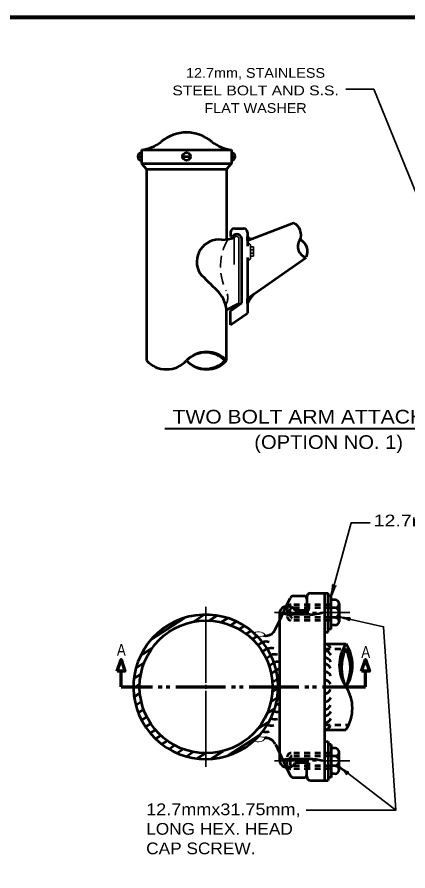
# Model space of a CAD drawing. Extents: x -32 to 824, y -12 to 532.
# Drawn here: x 407.2 to 527.1, y 262.9 to 525.2 of the extents above; entities that cross this region are included whole.
import ezdxf
from ezdxf.enums import TextEntityAlignment as Align

# ---------------------------------------------------------------- set-up
doc = ezdxf.new("R2010")
doc.units = 0
doc.header["$LTSCALE"] = 1.2
doc.header["$PDMODE"] = 32
doc.header["$PDSIZE"] = 0.6
for name, pattern in [('LONG_DASHED', [7.5, 6, -1.5]), ('MEDIUM_DASHED', [4.5, 3, -1.5]), ('SHORT_DASHED', [2.7, 1.5, -1.2])]:
    doc.linetypes.add(name, pattern=pattern)
doc.layers.add('1', color=7, linetype='Continuous', lineweight=13)

msp = doc.modelspace()

# ---------------------------------------------------------------- linework, layer by layer
at = {"layer": '1', "lineweight": 35}
for p, q in [((516.646, 503.069), (508.139, 503.069)), ((535.927, 455.696), (516.646, 503.069)), ((473.866, 449.258), (473.866, 457.442)), ((475.218, 437.258), (475.218, 457.058)), ((478.792, 451.117), (478.792, 455.136)), ((479.703, 453.725), (478.803, 453.725)), ((479.703, 452.707), (478.803, 452.707)), ((479.703, 451.807), (478.803, 451.807)), ((465.108, 320.687), (465.108, 344.049)), ((486.209, 342.287), (496.709, 342.287)), ((497.909, 342.287), (499.109, 342.287)), ((500.309, 342.287), (509.309, 342.287)), ((465.108, 318.887), (465.108, 320.087)), ((465.108, 294.849), (465.108, 318.287)), ((486.209, 296.687), (496.709, 296.687)), ((497.909, 296.687), (499.109, 296.687)), ((500.309, 296.687), (509.309, 296.687))]:
    msp.add_line(p, q, dxfattribs=at)
at = {"layer": '1', "lineweight": 53}
for p, q in [((445.409, 484.487), (473.009, 484.487)), ((445.409, 484.487), (445.409, 480.287)), ((473.009, 484.487), (473.009, 480.287)), ((444.216, 482.387), (445.109, 482.387)), ((445.409, 480.287), (473.009, 480.287)), ((445.409, 480.287), (446.909, 478.487)), ((458.301, 482.387), (460.101, 482.387)), ((473.009, 480.287), (471.509, 478.487)), ((473.309, 482.387), (474.153, 482.387)), ((446.909, 478.487), (446.909, 419.687)), ((446.909, 478.487), (471.509, 478.487)), ((471.509, 478.487), (471.509, 456.894)), ((477.889, 456.545), (492.012, 461.967)), ((472.709, 459.074), (472.709, 457.836)), ((473.909, 460.274), (476.689, 460.274)), ((477.889, 459.074), (477.889, 458.468)), ((472.709, 457.836), (473.309, 457.836)), ((476.15, 437.434), (476.15, 456.703)), ((477.889, 458.468), (477.889, 454.836)), ((477.889, 451.417), (477.889, 440.017)), ((477.889, 438.757), (495.908, 451.374)), ((477.889, 440.017), (477.889, 434.257)), ((471.509, 435.287), (475.218, 437.258)), ((472.709, 435.025), (476.15, 437.434)), ((471.509, 419.687), (471.509, 435.287)), ((472.709, 430.63), (472.709, 435.025)), ((472.709, 430.63), (477.889, 434.257)), ((489.786, 344.172), (490.984, 346.7)), ((492.069, 347.387), (495.209, 347.387)), ((496.109, 347.087), (496.109, 342.887)), ((497.309, 348.287), (502.709, 348.287)), ((501.509, 348.287), (501.509, 290.687)), ((502.709, 336.287), (502.709, 348.287)), ((503.609, 347.387), (502.709, 347.387)), ((503.609, 337.187), (503.609, 347.387)), ((496.709, 342.887), (496.709, 344.687)), ((504.809, 346.187), (503.609, 346.187)), ((504.809, 343.787), (503.609, 343.787)), ((506.009, 344.987), (506.009, 339.587)), ((461.196, 339.451), (464.592, 341.643)), ((466.201, 339.825), (468.599, 341.373)), ((487.709, 341.987), (487.709, 296.987)), ((497.009, 341.687), (491.609, 341.687)), ((496.709, 342.887), (492.509, 342.887)), ((448.346, 334.011), (458.497, 340.565)), ((469.839, 339.317), (471.835, 340.606)), ((472.812, 338.38), (474.585, 339.525)), ((486.423, 337.071), (487.709, 339.787)), ((504.809, 340.787), (503.609, 340.787)), ((504.809, 338.387), (503.609, 338.387)), ((475.341, 337.156), (476.975, 338.211)), ((477.527, 335.711), (479.072, 336.708)), ((501.509, 336.287), (502.709, 336.287)), ((503.609, 337.187), (502.709, 337.187)), ((479.426, 334.08), (480.913, 335.04)), ((481.067, 332.283), (482.52, 333.221)), ((445.094, 329.055), (448.633, 331.34)), ((482.466, 330.329), (483.906, 331.259)), ((501.509, 332.687), (508.109, 332.687)), ((483.627, 328.222), (485.074, 329.156)), ((443.691, 325.293), (446.231, 326.933)), ((484.544, 325.957), (486.017, 326.908)), ((443.058, 322.028), (445.197, 323.409)), ((485.198, 323.523), (486.724, 324.508)), ((442.911, 319.076), (444.828, 320.313)), ((485.558, 320.898), (487.168, 321.938)), ((443.124, 316.357), (444.902, 317.505)), ((485.561, 318.044), (487.306, 319.17)), ((443.632, 313.828), (445.319, 314.917)), ((485.092, 314.884), (487.062, 316.156)), ((444.394, 311.463), (446.024, 312.516)), ((483.889, 311.251), (486.289, 312.8)), ((445.39, 309.25), (446.986, 310.28)), ((446.607, 307.179), (448.191, 308.201)), ((480.992, 306.524), (484.624, 308.869)), ((448.043, 305.249), (449.633, 306.276)), ((449.703, 303.464), (451.32, 304.508)), ((471.804, 298.283), (481.642, 304.635)), ((501.509, 306.287), (508.109, 306.287)), ((451.6, 301.832), (453.269, 302.909)), ((486.465, 301.812), (487.709, 299.187)), ((501.509, 302.687), (502.709, 302.687)), ((502.709, 302.687), (502.709, 290.687)), ((503.609, 301.787), (502.709, 301.787)), ((503.609, 301.787), (503.609, 291.587)), ((453.759, 300.369), (455.513, 301.501)), ((456.225, 299.104), (458.113, 300.324)), ((459.072, 298.086), (461.186, 299.45)), ((462.449, 297.409), (464.991, 299.051)), ((466.717, 297.308), (470.493, 299.745)), ((504.809, 300.587), (503.609, 300.587)), ((506.009, 293.987), (506.009, 299.387)), ((497.009, 297.287), (491.609, 297.287)), ((504.809, 298.187), (503.609, 298.187)), ((489.786, 294.802), (490.984, 292.273)), ((496.709, 296.087), (492.509, 296.087)), ((496.109, 291.887), (496.109, 296.087)), ((496.709, 296.087), (496.709, 294.287)), ((504.809, 295.187), (503.609, 295.187)), ((492.069, 291.587), (495.209, 291.587)), ((503.609, 291.587), (502.709, 291.587)), ((504.809, 292.787), (503.609, 292.787)), ((497.309, 290.687), (502.709, 290.687))]:
    msp.add_line(p, q, dxfattribs=at)
at = {"layer": '1', "lineweight": 40}
msp.add_line((452.577, 398.821), (552.429, 398.821), dxfattribs=at)
at = {"layer": '1', "linetype": 'LONG_DASHED', "lineweight": 53}
for p, q in [((487.709, 339.786), (489.786, 344.172)), ((487.709, 299.187), (489.786, 294.802))]:
    msp.add_line(p, q, dxfattribs=at)
at = {"layer": '1', "linetype": 'SHORT_DASHED', "lineweight": 53}
for p, q in [((503.609, 344.687), (491.309, 344.687)), ((503.609, 343.787), (491.609, 343.787)), ((490.109, 343.487), (490.109, 341.087)), ((491.009, 341.387), (491.009, 343.187)), ((503.609, 339.887), (491.309, 339.887)), ((503.609, 340.787), (491.609, 340.787)), ((501.509, 331.187), (508.109, 331.187)), ((501.509, 307.787), (508.709, 307.787)), ((503.609, 299.087), (491.309, 299.087)), ((490.109, 295.487), (490.109, 297.887)), ((491.009, 297.587), (491.009, 295.787)), ((503.609, 298.187), (491.609, 298.187)), ((503.609, 294.287), (491.309, 294.287)), ((503.609, 295.187), (491.609, 295.187))]:
    msp.add_line(p, q, dxfattribs=at)
at = {"layer": '1', "lineweight": 70}
for p, q in [((439.109, 319.487), (439.109, 324.287)), ((514.109, 319.487), (514.109, 324.287)), ((439.109, 319.487), (448.709, 319.487)), ((450.509, 319.487), (451.709, 319.487)), ((452.909, 319.487), (454.109, 319.487)), ((455.909, 319.487), (471.209, 319.487)), ((473.009, 319.487), (474.209, 319.487)), ((475.409, 319.487), (476.609, 319.487)), ((478.409, 319.487), (493.709, 319.487)), ((495.509, 319.487), (496.709, 319.487)), ((497.909, 319.487), (499.109, 319.487)), ((500.909, 319.487), (514.109, 319.487))]:
    msp.add_line(p, q, dxfattribs=at)
at = {"layer": '1'}
msp.add_line((455.909, 319.487), (471.209, 319.487), dxfattribs=at)
at = {"layer": '1', "lineweight": 158}
msp.add_lwpolyline([(817.469, 525.227), (25.769, 525.127), (25.869, -0.873)], dxfattribs=at)
at = {"layer": '1', "lineweight": 53}
for points in [[(479.197, 457.054), (477.894, 456.554), (477.894, 457.786)], [(477.904, 437.276), (477.904, 438.78), (479.891, 440.171)]]:
    msp.add_lwpolyline(points, dxfattribs=at)
at = {"layer": '1', "lineweight": 35}
for points in [[(479.703, 451.807), (479.703, 454.625), (478.803, 454.625)], [(503.609, 347.387), (509.746, 369.903), (515.565, 369.903)], [(523.399, 281.579), (519.681, 337.946), (506.009, 341.002)], [(495.94, 281.579), (523.399, 281.579), (506.009, 294.949)]]:
    msp.add_lwpolyline(points, dxfattribs=at)
at = {"layer": '1', "lineweight": 70}
for points in [[(437.909, 324.287), (439.109, 327.887), (440.309, 324.287)], [(512.909, 324.287), (514.109, 327.887), (515.309, 324.287)]]:
    msp.add_lwpolyline(points, close=True, dxfattribs=at)
at = {"layer": '1', "lineweight": 53}
for centre, radius in [((459.201, 482.389), 1.2), ((465.209, 319.45), 20.4)]:
    msp.add_circle(centre, radius, dxfattribs=at)
for centre, radius, start, end in [((459.209, 477.854), 11.934, 49.18722, 130.81278), ((444.302, 495.954), 11.521, 275.5142, 308.08862), ((474.116, 495.954), 11.521, 231.91138, 264.4858), ((445.416, 482.355), 1.2, 90.3199, 269.6801), ((472.953, 482.355), 1.2, 272.67956, 87.32044), ((490.45, 458.385), 3.907, 333.96531, 66.42353), ((473.909, 459.074), 1.2, 90, 180), ((476.689, 459.074), 1.2, 0, 90), ((469.243, 449.977), 6.911, 83.22236, 210.1126), ((470.4, 467.016), 10.182, 268.07998, 289.90391), ((474.611, 456.972), 1.562, 350.09958, 146.42495), ((479.571, 459.244), 2.222, 221.01419, 260.32206), ((496.82, 454.716), 3.464, 145.65086, 254.73799), ((492.468, 453.242), 3.907, 333.96531, 66.42353), ((1790.939, 1774.354), 1877.735, 225.00367, 225.22952), ((461.891, 434.228), 9.676, 6.28285, 46.84726), ((488.119, 432.396), 11.321, 136.62273, 154.46868), ((465.359, 413.953), 8.408, 42.99091, 137.00909), ((465.049, 414.104), 8.079, 43.44505, 136.28697), ((453.059, 425.42), 8.408, 222.99091, 317.00909), ((465.359, 425.42), 8.408, 222.99091, 317.00909), ((465.075, 425.23), 8.07, 223.38031, 316.35171), ((492.068, 346.187), 1.2, 90, 154.65229), ((495.209, 346.487), 0.9, 0, 90), ((497.309, 347.087), 1.2, 90, 180), ((489.953, 341.993), 2.244, 111.08869, 180.15219), ((490.046, 339.764), 4.416, 78.23971, 101.76029), ((490.801, 342.28), 1.812, 19.5508, 85.42547), ((504.809, 344.987), 1.2, 0, 90), ((504.809, 344.976), 1.2, 270, 0), ((504.479, 342.287), 1.536, 282.40625, 77.59375), ((465.108, 319.449), 22.2, 42.84859, 309.02179), ((491.147, 348.865), 7.193, 250.874, 273.68302), ((496.766, 356.325), 14.641, 270.95318, 286.48773), ((504.809, 339.603), 1.2, 0, 90), ((504.809, 339.587), 1.2, 270, 0), ((483.574, 338.239), 3.079, 257.68223, 337.70907), ((465.108, 319.449), 22.2, 309.02189, 42.84853), ((483.682, 331.197), 2.172, 67.15515, 119.23791), ((485.169, 329.223), 2.172, 67.15515, 121.81596), ((501.404, 330.517), 2.172, 21.06434, 87.22086), ((501.477, 328.427), 2.172, 21.06434, 87.22086), ((517.944, 326.087), 11.844, 146.13542, 213.86458), ((520.398, 325.292), 13.63, 154.3728, 205.20801), ((496.111, 325.293), 13.367, 334.25624, 26.16295), ((498.317, 326.087), 11.844, 326.13542, 33.86458), ((486.232, 327.28), 2.172, 67.15515, 120.65847), ((501.44, 326.301), 2.172, 21.06434, 87.22086), ((487.143, 325.032), 2.172, 74.88502, 121.03631), ((501.404, 324.358), 2.172, 21.06434, 87.22086), ((487.902, 322.755), 2.172, 95.08372, 123.29121), ((501.44, 322.012), 2.172, 21.06434, 87.22086), ((501.367, 319.482), 2.172, 21.06434, 87.22086), ((501.367, 319.49), 2.172, 272.77914, 338.93566), ((498.274, 312.887), 11.844, 326.13542, 33.86458), ((501.44, 316.96), 2.172, 272.77914, 338.93566), ((487.902, 316.21), 2.172, 236.70879, 264.91628), ((501.404, 314.614), 2.172, 272.77914, 338.93566), ((486.232, 311.685), 2.172, 239.34153, 292.84485), ((487.143, 313.932), 2.172, 238.96369, 285.11497), ((501.44, 312.671), 2.172, 272.77914, 338.93566), ((501.477, 310.545), 2.172, 272.77914, 338.93566), ((485.169, 309.742), 2.172, 238.18404, 292.84485), ((501.404, 308.455), 2.172, 272.77914, 338.93566), ((483.682, 307.768), 2.172, 240.76209, 292.84485), ((483.601, 300.637), 3.079, 22.29093, 100.21406), ((504.809, 299.387), 1.2, 0, 90), ((504.809, 299.37), 1.2, 270, 0), ((489.953, 296.981), 2.244, 179.84781, 248.91131), ((491.147, 290.108), 7.193, 86.31698, 109.126), ((496.766, 282.648), 14.641, 73.51227, 89.04682), ((504.479, 296.687), 1.536, 282.40625, 77.59375), ((490.046, 299.21), 4.416, 258.23971, 281.76029), ((490.801, 296.693), 1.812, 274.57453, 340.4492), ((504.809, 293.997), 1.2, 0, 90), ((504.809, 293.987), 1.2, 270, 0), ((492.068, 292.787), 1.2, 205.34771, 270), ((495.209, 292.487), 0.9, 270, 0), ((497.309, 291.887), 1.2, 180, 270)]:
    msp.add_arc(centre, radius, start, end, dxfattribs=at)
at = {"layer": '1', "linetype": 'MEDIUM_DASHED', "lineweight": 35}
for centre, radius, start, end in [((486.581, 448.589), 16.938, 150.47291, 206.06704), ((467.061, 439.042), 4.792, 330.81735, 26.04877)]:
    msp.add_arc(centre, radius, start, end, dxfattribs=at)
at = {"layer": '1', "lineweight": 35}
for centre, radius, start, end in [((474.524, 457.188), 0.705, 349.37883, 158.91973), ((477.938, 454.929), 0.878, 13.64106, 87.59419), ((477.938, 451.324), 0.878, 272.40581, 346.35894)]:
    msp.add_arc(centre, radius, start, end, dxfattribs=at)
at = {"layer": '1', "linetype": 'SHORT_DASHED', "lineweight": 53}
for centre, radius, start, end in [((491.309, 343.487), 1.2, 90, 180), ((491.609, 343.187), 0.6, 90, 180), ((491.309, 341.087), 1.2, 180, 270), ((491.609, 341.387), 0.6, 180, 270), ((491.309, 297.887), 1.2, 90, 180), ((491.609, 297.587), 0.6, 90, 180), ((491.309, 295.487), 1.2, 180, 270), ((491.609, 295.787), 0.6, 180, 270)]:
    msp.add_arc(centre, radius, start, end, dxfattribs=at)
at = {"layer": '1'}
for centre, radius, start, end in [((481.35, 333.932), 2.483, 21.01512, 125.21688), ((471.46, 325.527), 13.431, 42.84853, 50.96996), ((482.647, 332.4), 2.629, 67.15515, 120.65847), ((471.46, 313.469), 13.431, 309.03004, 317.15147), ((482.647, 306.596), 2.629, 239.34153, 292.84485), ((481.35, 305.064), 2.483, 234.78312, 338.98488)]:
    msp.add_arc(centre, radius, start, end, dxfattribs=at)
at = {"layer": '1', "lineweight": 40}
for centre, major_axis, ratio, start_param, end_param in [((503.634, 348.737), (-0.383, -2.117), 0.122415, 0.8963533, 3.1415927), ((504.208, 348.617), (-0.758, -1.978), 0.07063, 3.1407148, 5.41811), ((507.359, 341.039), (-2.132, 0.284), 0.122415, 0.8963533, 3.1415927), ((507.266, 340.46), (2.011, -0.665), 0.07063, 6.2823074, 8.5597026), ((506.92, 293.928), (1.542, -1.452), 0.07063, 6.2823074, 8.5597026), ((507.249, 294.413), (-1.813, 1.158), 0.122415, 0.8963533, 3.1415927)]:
    msp.add_ellipse(centre, major_axis=major_axis, ratio=ratio, start_param=start_param, end_param=end_param, dxfattribs=at)
at = {"layer": '1'}
msp.add_point((501.509, 290.687), dxfattribs=at)

# ---------------------------------------------------------------- texts
for s, height, width, p in [('12.7mm, STAINLESS', 3, 1.1, (480.388, 506.581)), ('STEEL BOLT AND S.S.', 3, 1.2, (480.388, 501.181)), ('FLAT WASHER', 3, 1.1, (480.388, 495.781)), ('TWO BOLT ARM ATTACHMENT', 4.2, 1.15, (502.821, 400.361)), ('(OPTION NO. 1)', 4.2, 1.1, (502.821, 392.561))]:
    msp.add_text(s, height=height, dxfattribs=dict(at, width=width)).set_placement(p, align=Align.CENTER)
for s, width, p in [('12.7mm FLAT WASHER (TYP.)', 1.25, (516.627, 368.764)), ('A', 0.85, (437.817, 329.019)), ('A', 0.85, (512.837, 328.368)), ('12.7mmx31.75mm,', 1.15, (446.812, 280.039)), ('LONG HEX. HEAD', 1.1, (446.812, 274.039)), ('CAP SCREW.', 1.1, (446.812, 268.039))]:
    msp.add_text(s, height=3.6, dxfattribs=dict(at, width=width)).set_placement(p)

doc.saveas('drawing.dxf')
